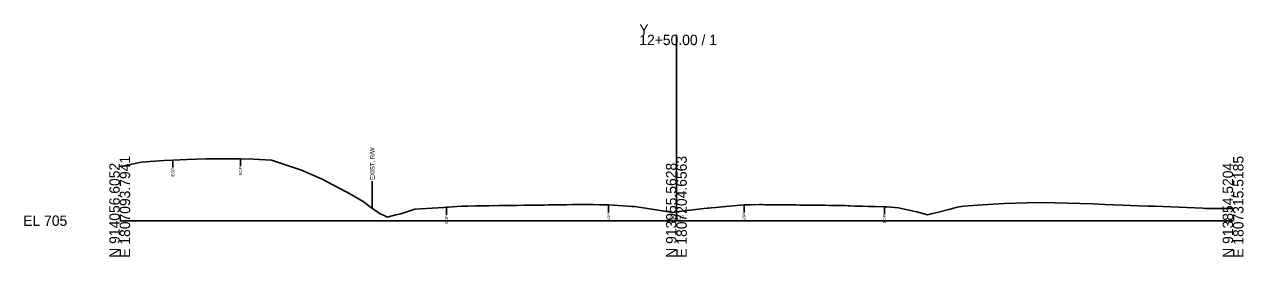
# Model space of a CAD drawing. Extents: x -26 to 3303, y -30 to 9580.
# Drawn here: x -25.7 to 302.8, y 2490.3 to 2553 of the extents above; entities that cross this region are included whole.
import ezdxf

# ---------------------------------------------------------------- set-up
doc = ezdxf.new("R2010")
doc.units = 0
for name, color, linetype in [('Exist Cross Section Cell', 7, 'Continuous'), ('Exist XS Center Line Elevation Label', 7, 'Continuous'), ('Exist XS Ground Line', 7, 'Continuous'), ('Old_Level_10', 7, 'Continuous')]:
    doc.layers.add(name, color=color, linetype=linetype)

msp = doc.modelspace()

# ---------------------------------------------------------------- linework, layer by layer
at = {"layer": 'Exist Cross Section Cell'}
for p, q in [((150, 2500), (150, 2550.17)), ((0, 2500), (150, 2500)), ((150, 2500), (300, 2500))]:
    msp.add_line(p, q, dxfattribs=at)
at = {"layer": 'Exist XS Ground Line'}
msp.add_lwpolyline([(0, 2514.69), (0.43, 2514.63), (5.74, 2515.76), (11.84, 2516.2), (14.33, 2516.37), (18.19, 2516.51), (23.29, 2516.69), (32.53, 2516.72), (36, 2516.57), (40.85, 2516.36), (42.01, 2515.96), (48.99, 2513.63), (54.34, 2511.28), (62.52, 2506.99), (65.86, 2505.04), (67.3, 2503.8), (68.73, 2502.86), (70.18, 2501.87), (71.26, 2501.4), (72.09, 2500.98), (74.06, 2501.47), (75.7, 2501.87), (77.35, 2502.42), (79.49, 2503.11), (87.3, 2503.58), (88.06, 2503.62), (88.58, 2503.64), (89.62, 2503.72), (92.18, 2503.92), (92.81, 2503.93), (93.83, 2503.95), (95.86, 2503.98), (98.73, 2504.03), (99.14, 2504.04), (99.59, 2504.04), (102.12, 2504.08), (103.14, 2504.09), (104.39, 2504.1), (105.49, 2504.12), (106.22, 2504.13), (107, 2504.14), (108.88, 2504.17), (110.7, 2504.19), (112.27, 2504.21), (114.43, 2504.23), (115.35, 2504.25), (115.82, 2504.25), (116.32, 2504.26), (118.16, 2504.29), (118.61, 2504.3), (119.02, 2504.31), (120.37, 2504.32), (121.81, 2504.34), (122.44, 2504.35), (123.91, 2504.36), (125.78, 2504.38), (127.58, 2504.41), (129.27, 2504.29), (131.74, 2504.24), (136.97, 2503.93), (137.96, 2503.86), (138.83, 2503.81), (149, 2502.24), (150, 2502.37), (157.39, 2503.28), (158.3, 2503.36), (158.64, 2503.39), (159.38, 2503.45), (160.73, 2503.58), (162.31, 2503.72), (168.25, 2504.26), (170.14, 2504.28), (172.32, 2504.35), (173.22, 2504.33), (173.82, 2504.32), (175.25, 2504.31), (176.54, 2504.3), (177.52, 2504.3), (178.76, 2504.29), (179.91, 2504.28), (180.54, 2504.27), (181.21, 2504.26), (182.3, 2504.25), (183.29, 2504.23), (184.08, 2504.22), (185.23, 2504.2), (185.82, 2504.2), (186.66, 2504.19), (187.6, 2504.18), (188.65, 2504.17), (189.38, 2504.16), (190.03, 2504.15), (191.13, 2504.14), (192.38, 2504.12), (192.94, 2504.11), (193.44, 2504.1), (195.39, 2504.08), (196.3, 2504.01), (196.79, 2503.99), (198.21, 2503.94), (199.75, 2503.91), (200.22, 2503.9), (201.76, 2503.87), (203.56, 2503.83), (205.78, 2503.77), (206.08, 2503.76), (206.67, 2503.7), (209.87, 2503.45), (213.11, 2502.74), (214.79, 2502.35), (215.8, 2502.09), (217.62, 2501.62), (218.68, 2501.87), (220.62, 2502.28), (223.79, 2503.14), (225.67, 2503.67), (227.4, 2503.88), (232.48, 2504.29), (238.41, 2504.68), (247.33, 2504.87), (251.94, 2504.8), (262.17, 2504.51), (265.47, 2504.39), (277.02, 2503.95), (279, 2503.88), (291.87, 2503.34), (292.53, 2503.32), (299.41, 2503.27), (300, 2503.26)], dxfattribs=at)
at = {"layer": 'Old_Level_10'}
for p, q in [((32.53, 2516.72), (32.53, 2514.67)), ((14.33, 2516.37), (14.33, 2514.32)), ((68.06, 2510.7), (68.06, 2503.3)), ((88.06, 2503.62), (88.06, 2501.57)), ((131.74, 2504.24), (131.74, 2502.19)), ((168.25, 2504.26), (168.25, 2502.21)), ((206.08, 2503.76), (206.08, 2501.71))]:
    msp.add_line(p, q, dxfattribs=at)

# ---------------------------------------------------------------- texts
at = {"layer": 'Exist Cross Section Cell'}
for s, p in [('Y', (140, 2550.17)), ('12+50.00 / 1', (140, 2547.37)), ('EL 705', (-26, 2498.6))]:
    msp.add_text(s, height=2.8, dxfattribs=at).set_placement(p)
for s, p in [('E 1807093.7941', (2.8, 2490)), ('E 1807204.6563', (152.8, 2490)), ('E 1807315.5185', (302.8, 2490)), ('N 914056.6052', (0, 2490)), ('N 913955.5628', (150, 2490)), ('N 913854.5204', (300, 2490))]:
    msp.add_text(s, height=2.8, rotation=90, dxfattribs=at).set_placement(p)
at = {"layer": 'Exist XS Center Line Elevation Label'}
msp.add_text('707.37', height=1, dxfattribs=at).set_placement((147.85, 2500.37))
at = {"layer": 'Old_Level_10'}
for s, height, p in [('EXIST. R/W', 1.181, (68.65, 2511)), ('EOP', 0.787, (14.72, 2511.92)), ('EOP', 0.787, (32.92, 2512.27)), ('EOP', 0.787, (88.45, 2499.17)), ('EOP', 0.787, (132.13, 2499.79)), ('EOP', 0.787, (168.64, 2499.81)), ('EOP', 0.787, (206.47, 2499.31))]:
    msp.add_text(s, height=height, rotation=90, dxfattribs=at).set_placement(p)

doc.saveas('drawing.dxf')
